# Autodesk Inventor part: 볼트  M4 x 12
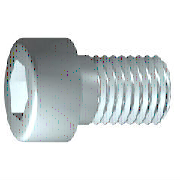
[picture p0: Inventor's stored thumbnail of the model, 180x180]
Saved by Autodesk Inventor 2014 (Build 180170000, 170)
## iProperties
IsCustomPart: 0
Created: 2015-12
Part Number: 볼트  M4 x 12
Material: 일반
Description: 6각머리 태핑 나사
Document SubType Name: Modeling
Standard: KS B 1003
Designer: mdu
Standards Organization: KS
Language: ko-KR
Size Designation: M 4 x 12
Categories: <MemberInstance><Categories><Category DisplayName="조임쇠" InternalName="e4da775c-781d-43d5-af7c-5136215cf5a6" Mnemonic="FSTN"><Category DisplayName="볼트" InternalN
Density: 1 g/cm^3
Mass: 0.284306 g
Surface Area: 3.30853 cm^2
Volume: 0.284306 cm^3
Appearance: 기본값
Author: mdu
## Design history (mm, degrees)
sketch "스케치1"
  geometry: L1 (-1, 0)-(12, 0); L2 (12, 0)-(12, 2); L3 (12, 2)-(1.75, 2); L4 (1.75, 2)-(1.32, 2); L5 (1.32, 2)-(0, 2); L6 (0, 2)-(0, 3.5); L7 (0, 3.5)-(-4, 3.5); L8 (-4, 3.5)-(-4, 1.732); L9 (-4, 1.732)-(-2, 1.732); L10 (-2, 1.732)-(-1, 0); L11 (-7.2, 0)-(15.2, 0) reference; L12 (0, -0.7)-(0, 4.2) reference; L13 (1.75, 2)-(0, 2)
  constraints: 22 end point, 6 parallel, 2 collinear, 2 perpendicular, 1 horizontal, 1 point on line
  dimensions: "d1" = 10.25 distance from line of L3.end L2 (= GEL); "d2" = 0.42952 distance of L4.end L3.end (computed from GAL); "d3" = 4 distance between parallel lines of L8 L6 (= KOH); "d4" = 2 distance of L8.end L9.end (= INTI); "d5" = 60 deg angle of L10 L1; "d6" = 4 diameter of L3 L1 (= GD); "d7" = 4 diameter of L5 L1 (= BDM); "d8" = 3.4641 diameter of L9 L1 (= 1.1547 x SW); "d9" = 7 diameter of L7 L1 (= KOD); "d26" = 12 distance between parallel lines of L12 L2 (= NLG)
revolve "본체" sketch "스케치1" stored, may be unused: angle "d10" = 90 deg
sketch "스케치2"
  geometry: L1 (0, -4.9)-(0, 4.9) reference; L2 (-4.9, 0)-(4.9, 0) reference; L3 (1.732, 0)-(0.866, -1.5); L4 (0.866, -1.5)-(-0.866, -1.5); L5 (-0.866, -1.5)-(-1.732, 0); L6 (-1.732, 0)-(-0.866, 1.5); L7 (-0.866, 1.5)-(0.866, 1.5); L8 (0.866, 1.5)-(1.732, 0); 2 further points
  constraints: 12 end point, 1 coincident, 1 horizontal alignment, 1 point on line, 12 other
extrude "슬롯" join sketch "스케치2" stored distance "d11" = 10; taper "d12" = 0 deg
workplane "Work Plane1"
fillet "Fillet2" dims "d30" = 0.1 (= R)
body "Solid1"
fillet "모깎기1" dims "d17" = 0.4 (= RR)
feature "스레드" dims "d13" = 10.25 (= GEL), "d14" = 0
chamfer "모따기1" distance "d15" = 0.42941 (= -0.5 x SPD + 0.5 x GD); stored, may be unused: second distance "d16" = 0.42941 (= GUL), angle "d27" = 45 deg
other parameters: "GD" = 4 (= NND) [user parameter; used in 2 equation terms], "NLG" = 12 [user parameter; used in 1 equation term], "GEL" = 10.25 [user parameter; used in 2 equation terms], "KOD" = 7 [user parameter; used in 1 equation term], "KOH" = 4 [user parameter; used in 1 equation term], "INTI" = 2 [user parameter; used in 1 equation term], "GAL" = 0.42941 (= 0.61345 x PTC) [user parameter; used in 1 equation term], "GUL" = 0.42941 (= 0.61345 x PTC) [user parameter; used in 1 equation term], "BDM" = 4 (= NND) [user parameter; used in 1 equation term], "SW" = 3 [user parameter; used in 2 equation terms], "RR" = 0.4 [user parameter; used in 1 equation term], "SPD" = 3.14117 (= NND - 1.2269 x PTC) [user parameter; used in 1 equation term], "d19" = 0, "d28" = 0, "d29" = 0, "R" = 0.1 [user parameter; used in 1 equation term], "PHH" = 0.2 [user parameter], "GD1" = 3.14117 (= THREADDIA - 1.2269 x PTC) [user parameter], "THREADDIA" = 4 [user parameter; used in 1 equation term], "FAWI" = 45 deg [user parameter], "TPU" = 14.28571 (computed from PTC) [user parameter], "PTC" = 0.7 [user parameter; used in 5 equation terms], "NND" = 4 [user parameter; used in 3 equation terms], "TOA" = 30 deg [user parameter], "E0" = 3.465 (= 1.155 x SW) [user parameter]
